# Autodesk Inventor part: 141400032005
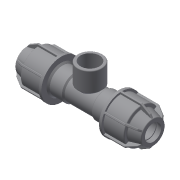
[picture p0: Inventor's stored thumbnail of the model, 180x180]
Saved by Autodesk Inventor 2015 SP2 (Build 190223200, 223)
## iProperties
Created: 2017-08
Part Number: 141400032005
Material: Generic
Description: PLASSON L.14 TEE FEMALE ADAPTOR (SILVER) 32 x 1/2" x 32
Document SubType Name: Modeling
Designer: KIM
Density: 1 g/cm^3
Appearance: Default
Author: KIM
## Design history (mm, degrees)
derived "141400.ipt"
feature "Solid1::141400.ipt"
feature "Solid2::141400.ipt"
tag "TaggingFeature1"
body "Solid1"
other parameters: "d1" = 32, "d2" = 56, "d4" = 15 deg, "d5" = 36.96, "d6" = 12.1968, "d10" = 61, "d16" = 32.64, "d17" = 2.8, "d22" = 51.2, "d24" = 2.8, "d25" = 54.9, "d26" = 45.75, "d27" = 2.8, "d28" = 135 deg, "d29" = 1.68, "d31" = 1.6, "d46" = 150 deg, "d49" = 3.05, "d50" = 0, "d58" = 0.96, "d61" = 360 deg, "d63" = 28.8, "d64" = 75, "d80" = 46.08, "d81" = 2.56, "d84" = 2.8, "d94" = 49, "d95" = 18.631, "d96" = 24.2203, "d97" = 18, "d98" = 16, "d99" = 21.79827, "d100" = 135 deg, "d108" = 1.6, "d111" = 0, "d_" = 32, "G_" = 18.631, "E_" = 61, "l_" = 56, "l_2" = 18, "A_" = 49
